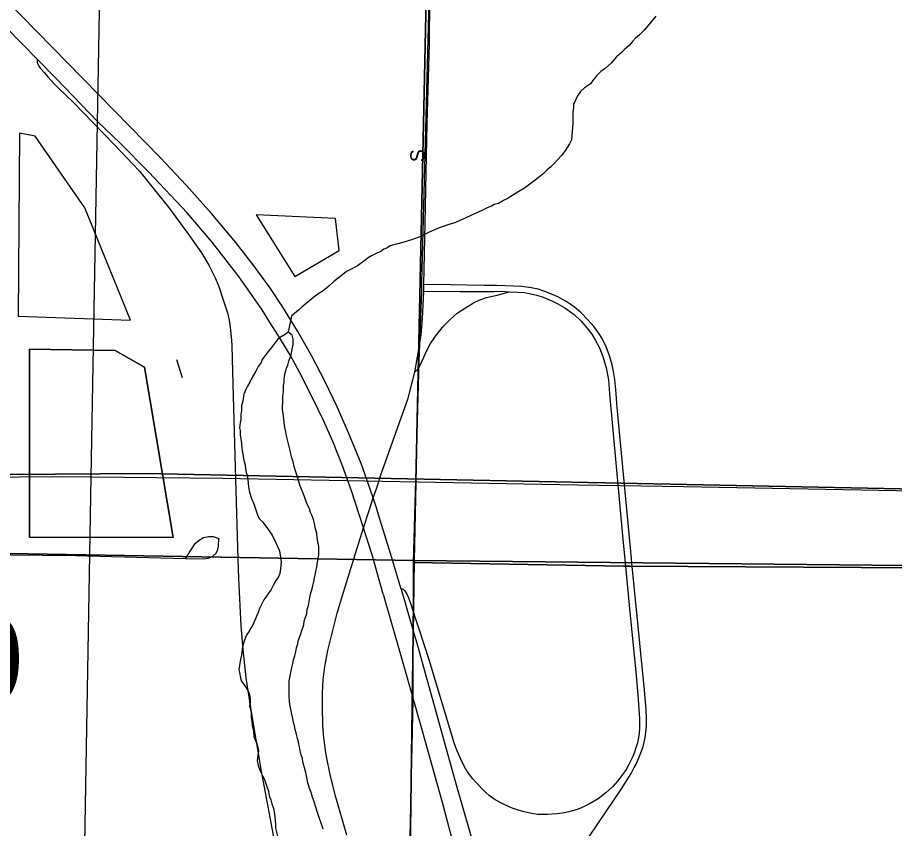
# Model space of a CAD drawing. Extents: x 0 to 68, y 0 to 52.9.
# Drawn here: x 43.605 to 44.214, y 35.105 to 35.667 of the extents above; entities that cross this region are included whole.
import ezdxf

# ---------------------------------------------------------------- set-up
doc = ezdxf.new("R2010")
doc.units = 0
for name, color, linetype in [('Default', 7, 'Continuous'), ('GM_X_County_Road', 7, 'Continuous'), ('GM_X_Minor_Lake', 7, 'Continuous'), ('GM_X_Minor_River', 7, 'Continuous'), ('GM_X_State_Route', 7, 'Continuous'), ('GM_X_Township', 7, 'Continuous'), ('GM_X_Township_Road', 7, 'Continuous'), ('GM_X_Township_Road_Text', 7, 'Continuous')]:
    doc.layers.add(name, color=color, linetype=linetype)

msp = doc.modelspace()

# ---------------------------------------------------------------- linework, layer by layer
at = {"layer": 'Default'}
for points in [[(43.64162, 32.7683), (43.64334, 34.0176), (43.64455, 34.6783), (43.65599, 35.34849), (43.66788, 36.0083), (43.67702, 36.44587), (43.68602, 36.84543), (43.69035, 37.04683), (43.69592, 37.28989), (43.69757, 37.31546), (43.70235, 37.35703), (43.70606, 37.38349), (43.71865, 37.45038), (43.791, 37.87267), (43.79415, 37.89545), (43.79589, 37.91564), (43.79763, 37.93547), (43.7985, 37.95966), (43.79937, 37.99098), (43.80146, 38.12323), (43.80732, 38.54108), (43.80967, 38.71924)], [(43.88793, 35.52467), (43.88887, 35.57152), (43.88935, 35.59375), (43.89094, 35.64952), (43.89084, 35.65938), (43.89262, 35.73479), (43.89362, 35.78401), (43.89443, 35.82078)], [(43.7604, 35.50627), (43.7564, 35.51138), (43.73953, 35.53148), (43.72212, 35.55111), (43.70411, 35.57019), (43.60766, 35.66876), (43.57856, 35.69858)], [(43.85882, 35.26723), (43.851, 35.29455), (43.8508, 35.29521), (43.84517, 35.31323), (43.83668, 35.33892), (43.83048, 35.35623), (43.82396, 35.37275), (43.81735, 35.38779), (43.81016, 35.40257), (43.80102, 35.42078), (43.79451, 35.43281), (43.78562, 35.44716), (43.77993, 35.45619), (43.77482, 35.46455), (43.75853, 35.4878), (43.74012, 35.51157), (43.72262, 35.53199), (43.69602, 35.56022), (43.67594, 35.58045), (43.66077, 35.59518), (43.63197, 35.62495), (43.6188, 35.63846), (43.59707, 35.66061)], [(43.6188, 35.63846), (43.61859, 35.6377), (43.61857, 35.63723), (43.61857, 35.63669), (43.6186, 35.63638), (43.61873, 35.6359), (43.61882, 35.63564), (43.61932, 35.63469), (43.61985, 35.63379), (43.621, 35.63222), (43.62348, 35.6293), (43.62594, 35.62632), (43.63056, 35.62119), (43.63345, 35.61843), (43.64365, 35.60868), (43.67233, 35.57908), (43.68498, 35.56569), (43.6899, 35.56062), (43.70088, 35.54678), (43.7098, 35.53579), (43.7232, 35.51765), (43.73256, 35.50414), (43.73767, 35.4957), (43.74214, 35.48691), (43.74466, 35.48084), (43.74777, 35.47148), (43.7506, 35.46246), (43.75176, 35.45743), (43.75254, 35.45247), (43.75348, 35.44348), (43.75371, 35.4396), (43.75429, 35.41293), (43.75621, 35.34708), (43.75789, 35.29172), (43.75831, 35.27806), (43.76007, 35.24522), (43.7613, 35.22883), (43.76352, 35.20923), (43.76636, 35.18971), (43.77412, 35.14433), (43.79941, 35.00854)], [(43.79104, 35.46337), (43.78919, 35.46637), (43.78008, 35.47999), (43.76853, 35.4959), (43.7604, 35.50627)], [(43.88078, 35.42128), (43.88264, 35.42315), (43.88403, 35.4252), (43.8858, 35.42911), (43.88899, 35.43638), (43.8916, 35.44118), (43.89466, 35.44573), (43.89663, 35.44849), (43.90087, 35.45348), (43.9055, 35.45813), (43.91018, 35.46217), (43.91586, 35.466), (43.92144, 35.46935), (43.92573, 35.47149), (43.93038, 35.47317), (43.93787, 35.47489), (43.94127, 35.47569), (43.9463, 35.47709), (43.95207, 35.4769), (43.95694, 35.47652), (43.9612, 35.47579), (43.96539, 35.47468), (43.96986, 35.47328), (43.97628, 35.47058), (43.98, 35.46871), (43.98485, 35.46593), (43.99119, 35.46128), (43.99613, 35.45663), (44.00019, 35.45221), (44.00354, 35.44774), (44.00608, 35.44335), (44.00891, 35.43832), (44.01128, 35.43218), (44.01348, 35.42432), (44.01507, 35.41611), (44.01583, 35.40618), (44.02514, 35.30531), (44.02669, 35.28906), (44.02949, 35.25964), (44.03435, 35.21071), (44.03573, 35.19435), (44.03668, 35.1807), (44.03661, 35.17417), (44.03645, 35.17081), (44.03597, 35.16778), (44.03517, 35.16403), (44.03422, 35.1606), (44.03318, 35.15765), (44.03199, 35.15462), (44.02935, 35.14896), (44.02729, 35.14545), (44.02441, 35.14138), (44.02138, 35.13755), (44.01811, 35.13379), (44.01325, 35.1294), (44.00791, 35.12526), (44.00241, 35.1219), (43.99779, 35.11966), (43.99403, 35.11807), (43.98957, 35.11663), (43.9847, 35.11551), (43.9796, 35.11479), (43.97282, 35.11431), (43.96899, 35.11423), (43.96604, 35.11439), (43.96301, 35.11478), (43.95958, 35.11542), (43.9567, 35.11614), (43.95319, 35.11701), (43.95033, 35.11797), (43.94705, 35.11924), (43.94123, 35.12203), (43.93652, 35.12459), (43.93237, 35.12753), (43.93014, 35.12945), (43.92718, 35.1324), (43.92296, 35.13678), (43.92101, 35.13907), (43.91713, 35.14426), (43.91514, 35.14747), (43.91234, 35.15321), (43.90995, 35.15903), (43.90927, 35.16085)], [(43.88698, 35.47758), (43.91196, 35.47741), (43.92612, 35.47741), (43.93594, 35.47742), (43.94083, 35.4775), (43.9463, 35.47709)], [(43.99668, 35.0913), (44.02419, 35.13222), (44.03088, 35.14266), (44.03304, 35.14684), (44.0343, 35.14928), (44.03622, 35.15358), (44.03797, 35.15821), (44.03916, 35.1614), (44.03996, 35.16459), (44.04059, 35.16755), (44.04115, 35.17138), (44.04155, 35.17584), (44.04162, 35.18063), (44.04118, 35.18748), (44.04022, 35.2006), (44.03679, 35.23329), (44.03143, 35.28901), (44.03113, 35.29211), (44.02114, 35.3967), (44.02015, 35.40938), (44.01943, 35.41632), (44.01863, 35.42175), (44.01775, 35.42653), (44.01591, 35.43275), (44.01351, 35.43898), (44.01064, 35.44472), (44.00872, 35.44798), (44.00508, 35.4527), (44.0009, 35.45776), (43.99626, 35.4624), (43.9912, 35.4666), (43.98579, 35.47032), (43.98006, 35.47355), (43.97407, 35.4762), (43.97099, 35.47734), (43.96622, 35.47886), (43.96147, 35.47981), (43.95499, 35.48072), (43.94922, 35.4811), (43.93732, 35.48147), (43.92872, 35.48157), (43.90574, 35.48191), (43.88708, 35.48229)], [(43.85404, 35.32726), (43.85191, 35.3342), (43.84622, 35.35005), (43.8434, 35.35783), (43.83479, 35.3792), (43.82683, 35.39726), (43.81831, 35.41504), (43.80922, 35.43251), (43.79951, 35.44963), (43.79104, 35.46337)], [(43.71945, 35.4174), (43.71547, 35.42991)], [(43.83861, 35.29249), (43.83956, 35.29551), (43.84517, 35.31323), (43.84898, 35.32522), (43.85191, 35.3342), (43.85456, 35.34184), (43.85697, 35.34926), (43.87603, 35.40331), (43.88078, 35.42128)], [(43.87134, 35.27081), (43.86397, 35.29486), (43.85554, 35.32238), (43.85404, 35.32726)], [(43.83149, 35.26928), (43.83624, 35.28501), (43.83829, 35.29149)], [(43.83829, 35.29149), (43.83861, 35.29249)], [(43.90927, 35.16085), (43.90805, 35.16411), (43.90635, 35.16948), (43.89058, 35.22167), (43.88392, 35.24227), (43.88149, 35.24991), (43.87966, 35.25562), (43.87848, 35.25929), (43.87724, 35.26258), (43.87659, 35.26438), (43.87541, 35.26724), (43.87481, 35.2684), (43.87435, 35.2691), (43.87384, 35.26968), (43.87335, 35.27012), (43.87292, 35.27038), (43.87226, 35.27067), (43.87134, 35.27081)], [(43.83358, 35.10006), (43.82588, 35.12626), (43.82217, 35.1408), (43.81914, 35.15575), (43.81749, 35.16755), (43.81694, 35.17634), (43.81666, 35.18923), (43.81666, 35.19842), (43.81706, 35.20789), (43.8183, 35.21695), (43.82035, 35.22806), (43.82281, 35.23836), (43.82692, 35.25413), (43.83149, 35.26928)]]:
    msp.add_lwpolyline(points, dxfattribs=at)
for points in [[(43.11555, 36.67874), (44.34414, 36.66665), (44.32023, 35.33817), (43.69327, 35.3509), (43.1026, 35.34663), (43.11455, 36.64024)], [(42.83718, 36.36115), (43.90273, 36.34073), (43.8802, 35.29067), (42.82102, 35.30893)], [(43.90273, 36.34073), (44.95281, 36.32851), (44.93588, 35.27966), (44.90228, 35.2801), (43.8802, 35.29067)], [(43.1026, 35.34663), (43.69327, 35.3509), (44.32023, 35.33817), (44.30324, 34.00462), (43.08734, 34.03057), (43.1022, 35.31613)], [(42.82102, 35.30893), (43.8802, 35.29067), (43.86646, 34.27144), (43.86565, 34.24064), (42.80414, 34.29415)], [(43.8802, 35.29067), (44.90228, 35.2801), (44.84933, 34.26177), (43.86646, 34.27144)]]:
    msp.add_lwpolyline(points, close=True, dxfattribs=at)
at = {"layer": 'GM_X_County_Road'}
for points in [[(43.88708, 35.48229), (43.88793, 35.52467)], [(43.88078, 35.42128), (43.88337, 35.43596), (43.88501, 35.44735), (43.88597, 35.45848), (43.88652, 35.46793), (43.88698, 35.47758)], [(43.88698, 35.47758), (43.88708, 35.48229)]]:
    msp.add_lwpolyline(points, dxfattribs=at)
at = {"layer": 'GM_X_Minor_Lake'}
for points in [[(43.60634, 35.5873), (43.6055, 35.46031), (43.68345, 35.45749)], [(43.60634, 35.5873), (43.6055, 35.46031), (43.68345, 35.45749), (43.65165, 35.53539), (43.61717, 35.58518), (43.60634, 35.5873)], [(43.68345, 35.45749), (43.65165, 35.53539), (43.61717, 35.58518), (43.60634, 35.5873)], [(43.77058, 35.53054), (43.79749, 35.48766), (43.82822, 35.50583)], [(43.82822, 35.50583), (43.82562, 35.52796), (43.77058, 35.53054)], [(43.77058, 35.53054), (43.79749, 35.48766), (43.82822, 35.50583), (43.82562, 35.52796), (43.77058, 35.53054)], [(43.61331, 35.43733), (43.61324, 35.30671), (43.71292, 35.30648), (43.69318, 35.42484)], [(43.61331, 35.43733), (43.67276, 35.43628), (43.69318, 35.42484), (43.71292, 35.30648), (43.61324, 35.30671), (43.61331, 35.43733)], [(43.69318, 35.42484), (43.67276, 35.43628), (43.61331, 35.43733)]]:
    msp.add_lwpolyline(points, dxfattribs=at)
at = {"layer": 'GM_X_Minor_River'}
for points in [[(44.04807, 35.66832), (44.0436, 35.66314), (44.03994, 35.65876), (44.03669, 35.65558), (44.03386, 35.6532), (44.03182, 35.65081), (44.02939, 35.64802), (44.02655, 35.64564), (44.02371, 35.64285), (44.02046, 35.64007), (44.01721, 35.63609), (44.01275, 35.63212), (44.00992, 35.63014), (44.00707, 35.62735), (44.00464, 35.62456), (44.0026, 35.62137), (43.99855, 35.6186), (43.99571, 35.61622), (43.99367, 35.61302), (43.99244, 35.61062), (43.9908, 35.60702), (43.99078, 35.60502), (43.99035, 35.6018), (43.99031, 35.59819), (43.99027, 35.59417), (43.98935, 35.58252), (43.98812, 35.57972), (43.98526, 35.57533), (43.98241, 35.57174), (43.97997, 35.56896), (43.97753, 35.56617), (43.9751, 35.56378), (43.97267, 35.5618), (43.96983, 35.55901), (43.9674, 35.55703), (43.96416, 35.55465), (43.96051, 35.55188), (43.95687, 35.5491), (43.95283, 35.54673), (43.94918, 35.54436), (43.94554, 35.54199), (43.94231, 35.54041), (43.93868, 35.53844), (43.93585, 35.53767), (43.93383, 35.53648), (43.93101, 35.5353), (43.92778, 35.53373)], [(43.92778, 35.53373), (43.92414, 35.53216), (43.9201, 35.53019), (43.91566, 35.52823), (43.91203, 35.52666), (43.9084, 35.52509), (43.90437, 35.52393), (43.90114, 35.52275), (43.89751, 35.52159), (43.89428, 35.52001), (43.88984, 35.51805), (43.88419, 35.51529), (43.87773, 35.51295), (43.87249, 35.5114), (43.86806, 35.51024), (43.86524, 35.50946), (43.86322, 35.50868), (43.8612, 35.5075), (43.85918, 35.50671), (43.85716, 35.50513), (43.85433, 35.50395), (43.85069, 35.50198), (43.84827, 35.5008), (43.84543, 35.49842), (43.84098, 35.49525), (43.83654, 35.49288), (43.83331, 35.49131), (43.82844, 35.48734), (43.82439, 35.48417), (43.82114, 35.48098), (43.81709, 35.47781), (43.81345, 35.47544), (43.81062, 35.47346), (43.80778, 35.47108), (43.80535, 35.46909), (43.80252, 35.46671), (43.80008, 35.46432), (43.79724, 35.46194), (43.79522, 35.46035), (43.7927, 35.44913)], [(43.79236, 35.37438), (43.79159, 35.3772), (43.79122, 35.38002), (43.79044, 35.38284), (43.79007, 35.38606), (43.7897, 35.38928), (43.78933, 35.3925), (43.78895, 35.39532), (43.78898, 35.39773), (43.789, 35.40014), (43.78902, 35.40255), (43.78905, 35.40496), (43.78948, 35.40777), (43.7895, 35.41018), (43.78952, 35.41219), (43.78994, 35.41419), (43.78996, 35.4162), (43.7904, 35.42022), (43.79123, 35.42222), (43.79165, 35.42422), (43.79247, 35.42622), (43.7933, 35.42903), (43.79413, 35.43143), (43.79495, 35.43343), (43.79538, 35.43584), (43.79581, 35.43825), (43.79623, 35.44065), (43.79627, 35.44427), (43.79549, 35.44709), (43.7927, 35.44913), (43.79067, 35.44754), (43.78784, 35.44596), (43.78541, 35.44398), (43.78256, 35.44039), (43.78134, 35.43839), (43.7789, 35.43561), (43.77686, 35.43282), (43.77482, 35.43002), (43.774, 35.42802), (43.77196, 35.42523), (43.77032, 35.42203), (43.76869, 35.41924), (43.76705, 35.41644), (43.76623, 35.41444), (43.76459, 35.41164), (43.76336, 35.40924), (43.76213, 35.40604), (43.76128, 35.40123), (43.76044, 35.39802), (43.76041, 35.39481), (43.75998, 35.392), (43.75994, 35.38838), (43.75952, 35.38638), (43.75909, 35.38276), (43.75947, 35.38075), (43.75944, 35.37753), (43.76021, 35.37391), (43.76056, 35.36868), (43.76132, 35.36425), (43.76208, 35.36023), (43.76285, 35.357), (43.76323, 35.35419), (43.76361, 35.35177), (43.76439, 35.34975), (43.76476, 35.34694), (43.76513, 35.34372), (43.7655, 35.3401), (43.76588, 35.33808), (43.76745, 35.33365), (43.76902, 35.33001), (43.77058, 35.32518), (43.77175, 35.32154), (43.77294, 35.31952), (43.77493, 35.31749), (43.7781, 35.31344), (43.78167, 35.30818), (43.78442, 35.30252), (43.78679, 35.29728), (43.78755, 35.29285), (43.78792, 35.28963), (43.78747, 35.28481), (43.78703, 35.2816), (43.7858, 35.2788), (43.78417, 35.27681), (43.78253, 35.27361), (43.7809, 35.27041), (43.77926, 35.26802), (43.77723, 35.26522), (43.776, 35.26323), (43.77436, 35.26003), (43.77272, 35.25683), (43.77189, 35.25443), (43.77107, 35.25243), (43.76984, 35.24963), (43.7686, 35.24643), (43.76697, 35.24363), (43.76574, 35.24163), (43.76411, 35.23924), (43.76329, 35.23724), (43.76246, 35.23524), (43.76163, 35.23243)], [(43.81705, 35.10406), (43.81588, 35.10769), (43.81431, 35.11212), (43.81314, 35.11575), (43.81197, 35.11938), (43.8108, 35.12301), (43.80963, 35.12624), (43.80885, 35.12946), (43.80768, 35.13269), (43.80651, 35.13632), (43.80574, 35.13994), (43.80497, 35.14357), (43.8042, 35.14679), (43.80303, 35.15082), (43.80266, 35.15324), (43.80188, 35.15566), (43.8011, 35.15848), (43.80073, 35.1613), (43.79995, 35.16452), (43.79917, 35.16694), (43.79879, 35.16895), (43.79841, 35.17096), (43.79763, 35.17338), (43.79725, 35.1758), (43.79647, 35.17822), (43.7961, 35.18104), (43.79532, 35.18386), (43.79494, 35.18627), (43.79417, 35.18949), (43.7938, 35.19271), (43.79343, 35.19633), (43.79346, 35.19955), (43.7935, 35.20276), (43.79352, 35.20517), (43.79354, 35.20718), (43.79524, 35.21641), (43.79607, 35.21921), (43.79649, 35.22162), (43.79732, 35.22442), (43.79816, 35.22723), (43.79859, 35.23004), (43.79942, 35.23284), (43.79984, 35.23485), (43.80067, 35.23725), (43.80149, 35.23965), (43.80232, 35.24206), (43.80357, 35.24606), (43.80399, 35.24847), (43.80482, 35.25127), (43.80565, 35.25368), (43.80608, 35.25649), (43.80691, 35.25929), (43.80734, 35.2621), (43.80777, 35.26491), (43.80861, 35.26811), (43.80944, 35.27092), (43.80986, 35.27333), (43.81069, 35.27613), (43.81112, 35.27854), (43.81154, 35.28054), (43.81197, 35.28295), (43.8128, 35.28616), (43.81324, 35.28937), (43.81367, 35.29217), (43.81409, 35.29458), (43.81412, 35.29739), (43.81415, 35.30021), (43.81338, 35.30383), (43.813, 35.30625), (43.81263, 35.30947), (43.81186, 35.31269), (43.81109, 35.31632), (43.81031, 35.31914), (43.80914, 35.32196), (43.80835, 35.32398), (43.80757, 35.3264), (43.80679, 35.32842), (43.8056, 35.33084), (43.80404, 35.33487), (43.80326, 35.33729), (43.80208, 35.34012), (43.8009, 35.34294), (43.80012, 35.34536), (43.79701, 35.35585), (43.79623, 35.35907), (43.79546, 35.36189), (43.79468, 35.36471), (43.79391, 35.36793), (43.79314, 35.37156), (43.79236, 35.37438)], [(43.76163, 35.23243), (43.7608, 35.22923), (43.76035, 35.22521), (43.75951, 35.2208), (43.75864, 35.21478), (43.75903, 35.21277), (43.75979, 35.20914), (43.76018, 35.20713), (43.76216, 35.2043), (43.76414, 35.20146), (43.76572, 35.19863), (43.76648, 35.1946), (43.76646, 35.19179), (43.76603, 35.18979), (43.76681, 35.18656), (43.76719, 35.18455), (43.76716, 35.18174), (43.76754, 35.17892), (43.76791, 35.1761), (43.76867, 35.17208), (43.76904, 35.16805), (43.76982, 35.16604), (43.771, 35.16361), (43.77178, 35.16079), (43.77216, 35.15838), (43.77173, 35.15557), (43.77129, 35.15155), (43.77206, 35.14833), (43.77323, 35.1451), (43.77639, 35.13864), (43.77795, 35.1338), (43.77912, 35.13057), (43.7795, 35.12856), (43.77989, 35.12655), (43.78067, 35.12453), (43.78144, 35.12171), (43.78262, 35.11848), (43.78339, 35.11486), (43.78375, 35.11043), (43.78412, 35.10721), (43.78409, 35.1048), (43.78564, 35.09835)]]:
    msp.add_lwpolyline(points, dxfattribs=at)
at = {"layer": 'GM_X_State_Route'}
for points in [[(43.87134, 35.27081), (43.8796, 35.24176), (43.88246, 35.23168), (43.90949, 35.13497), (43.92645, 35.07564)], [(43.85882, 35.26723), (43.87264, 35.21896), (43.87939, 35.19538), (43.88428, 35.17827), (43.8997, 35.12285), (43.90881, 35.08863)]]:
    msp.add_lwpolyline(points, dxfattribs=at)
at = {"layer": 'GM_X_Township'}
for points in [[(45.98487, 35.25468), (45.19609, 35.27373), (44.67116, 35.28291), (44.03026, 35.28678), (44.02565, 35.2866), (43.87984, 35.28929), (43.8838, 35.42872), (43.88554, 35.47765), (43.88559, 35.48361), (43.89433, 35.82141)], [(43.82555, 31.14308), (43.84116, 32.12518), (43.84157, 32.15139), (43.84801, 32.65058), (43.84836, 32.67758), (43.85768, 33.1798), (43.85826, 33.20494), (43.86306, 33.73951), (43.8693, 34.2426), (43.87279, 34.5425), (43.87416, 34.73517), (43.87728, 34.86863), (43.87373, 34.92293), (43.87405, 34.94019), (43.87961, 35.19356), (43.87966, 35.21517), (43.87984, 35.28929), (44.02565, 35.2866), (44.03026, 35.28678), (44.67116, 35.28291), (45.19609, 35.27373), (45.98487, 35.25468)]]:
    msp.add_lwpolyline(points, dxfattribs=at)
at = {"layer": 'GM_X_Township_Road'}
for points in [[(43.10625, 35.34577), (43.11563, 35.34557), (43.11973, 35.34548), (43.24691, 35.3466), (43.39051, 35.34699), (43.50127, 35.34778), (43.63254, 35.34888), (43.74739, 35.34771), (43.99351, 35.34314), (44.06735, 35.34196), (44.22732, 35.33899), (44.46523, 35.33417), (44.78106, 35.32815), (44.99612, 35.32175)], [(43.72147, 35.29203), (43.72837, 35.30232), (43.73109, 35.30483), (43.73416, 35.30663), (43.73779, 35.30728), (43.74071, 35.30735), (43.74471, 35.30581)], [(43.72147, 35.29203), (43.73372, 35.29171), (43.73718, 35.29219), (43.74047, 35.29358), (43.74279, 35.29563), (43.7441, 35.29813), (43.74437, 35.30046), (43.74471, 35.30581)], [(43.5776, 35.2948), (43.64503, 35.29397), (43.72147, 35.29203)]]:
    msp.add_lwpolyline(points, dxfattribs=at)

# ---------------------------------------------------------------- texts
at = {"layer": 'Default'}
msp.add_text('S', height=0.01, rotation=90, dxfattribs=at).set_placement((43.88758, 35.56714))
at = {"layer": 'GM_X_Township_Road_Text'}
msp.add_text('T-80', height=0.06, rotation=359.29306, dxfattribs=at).set_placement((43.44377, 35.19373))

doc.saveas('drawing.dxf')
